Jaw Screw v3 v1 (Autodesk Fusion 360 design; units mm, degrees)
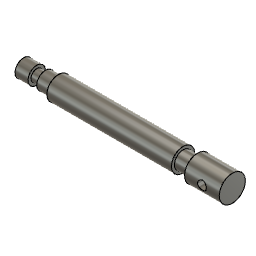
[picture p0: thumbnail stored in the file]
sketch "Sketch1" plane through (0, 0, 0) normal (0, 0, 1) x axis (1, 0, 0)
  line L1 (-164.9147, 0) -> (150.4957, 0)
  line L2 (0, 124.0284) -> (0, -129.5156)
  line L3 (-70, 6) -> (-70, 0)
  line L4 (-61, 6) -> (-70, 6)
  line L5 (-61, 4) -> (-61, 6)
  line L6 (-55, 4) -> (-61, 4)
  line L7 (-55, 6) -> (-55, 4)
  line L8 (-46, 6) -> (-55, 6)
  line L9 (-46, 8) -> (-46, 6)
  line L10 (40, 8) -> (-46, 8)
  line L11 (40, 6) -> (40, 8)
  line L12 (50, 6) -> (40, 6)
  line L13 (50, 9) -> (50, 6)
  line L14 (74, 9) -> (50, 9)
  line L15 (74, 0) -> (74, 9)
  line L16 (-70, 0) -> (74, 0)
  point P1 (0, 0)
  point P6 (-70, 0)
  point P19 (74, 0)
  point P7 (-70, 6)
  point P8 (-61, 6)
  point P9 (-61, 4)
  point P10 (-55, 4)
  point P11 (-55, 6)
  point P12 (-46, 6)
  point P13 (-46, 8)
  point P14 (40, 8)
  point P15 (40, 6)
  point P16 (50, 6)
  point P17 (50, 9)
  point P18 (74, 9)
  horizontal L1
  coincident P1 L1
  perpendicular L1 L2
  coincident P1 L2
  coincident L1 P6
  coincident L1 P19
  perpendicular L1 L15
  perpendicular L3 L16
  horizontal L14
  vertical L13
  horizontal L12
  horizontal L10
  vertical L11
  vertical L9
  horizontal L8
  vertical L7
  horizontal L6
  vertical L5
  dimension "d1" distance P6 P7 = 6
  dimension "d2" distance P7 P8 = 9
  dimension "d4" distance P8 P9 = 2
  dimension "d5" distance P9 P10 = 6
  dimension "d6" distance P10 P11 = 2
  dimension "d7" distance P11 P12 = 9
  dimension "d8" distance P12 P13 = 2
  dimension "d9" distance P13 P14 = 86
  dimension "d10" distance P14 P15 = 2
  dimension "d11" distance P15 P16 = 10
  dimension "d12" distance P16 P17 = 3
  dimension "d13" distance P17 P18 = 24
  dimension "d22" distance P7 P18 = 144
revolve "Revolve1" sketch "Sketch1" AlongAngle 360
sketch "Sketch2" plane through (0, 0, 0) normal (0, 0, 1) x axis (1, 0, 0)
  line L1 (74, 9) -> (74, -9)
  circle C1 centre (62, 0) radius 3
  point P2 (62, 0)
  dimension "d17" diameter C1 = 6
  dimension "d18" distance P2 L1 = 12
extrude "Extrude1" cut sketch "Sketch2" profile of C1 distance 9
